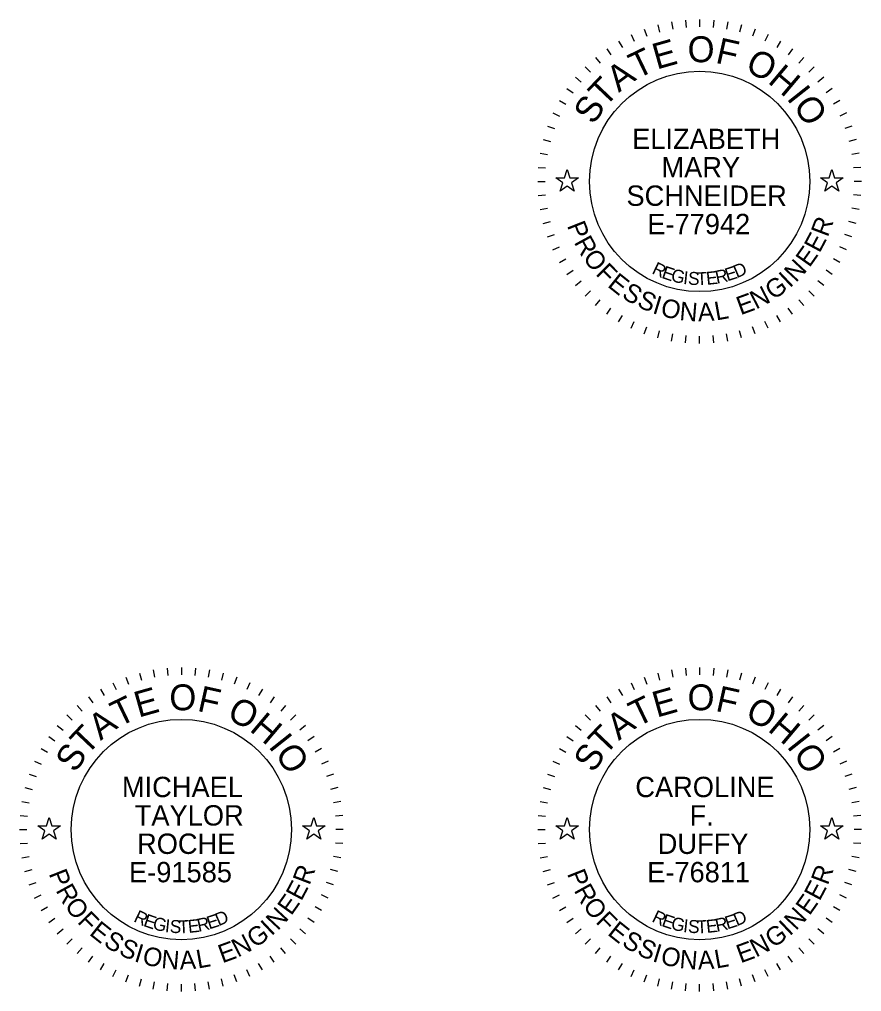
# Model space of a CAD drawing. Extents: x -21.9 to 47.3, y 14.1 to 48.7.
# Drawn here: x 24.13 to 28.67, y 20.77 to 26.02 of the extents above; entities that cross this region are included whole.
import ezdxf

# ---------------------------------------------------------------- set-up
doc = ezdxf.new("R2010")
doc.units = 0
doc.layers.add('SH_Seal', color=7, linetype='Continuous')

msp = doc.modelspace()

# ---------------------------------------------------------------- linework, layer by layer
at = {"layer": 'SH_Seal'}
for p, q in [((27.5735, 25.989), (27.5839, 25.9503)), ((27.6481, 26.0055), (27.655, 25.9661)), ((27.7237, 26.0155), (27.7272, 25.9756)), ((27.8, 26.0188), (27.8, 25.9788)), ((27.8763, 26.0155), (27.8728, 25.9756)), ((27.9519, 26.0055), (27.945, 25.9661)), ((28.0265, 25.989), (28.0161, 25.9503)), ((27.4302, 25.9368), (27.4471, 25.9006)), ((27.5007, 25.966), (27.5144, 25.9284)), ((28.0993, 25.966), (28.0856, 25.9284)), ((28.1698, 25.9368), (28.1529, 25.9006)), ((27.3625, 25.9016), (27.3825, 25.8669)), ((28.2375, 25.9016), (28.2175, 25.8669)), ((27.2981, 25.8605), (27.3211, 25.8278)), ((28.3019, 25.8605), (28.2789, 25.8278)), ((27.2376, 25.8141), (27.2633, 25.7834)), ((28.3624, 25.8141), (28.3367, 25.7834)), ((27.1813, 25.7625), (27.2096, 25.7342)), ((28.4187, 25.7625), (28.3904, 25.7342)), ((27.1297, 25.7062), (27.1604, 25.6805)), ((28.4703, 25.7062), (28.4396, 25.6805)), ((27.0832, 25.6457), (27.116, 25.6227)), ((28.5168, 25.6457), (28.484, 25.6227)), ((27.0422, 25.5813), (27.0769, 25.5613)), ((28.5578, 25.5813), (28.5231, 25.5613)), ((27.007, 25.5136), (27.0432, 25.4967)), ((28.593, 25.5136), (28.5568, 25.4967)), ((26.9778, 25.4431), (27.0154, 25.4294)), ((28.6222, 25.4431), (28.5846, 25.4294)), ((26.9548, 25.3703), (26.9935, 25.3599)), ((28.6452, 25.3703), (28.6065, 25.3599)), ((26.9383, 25.2957), (26.9777, 25.2888)), ((28.6617, 25.2957), (28.6223, 25.2888)), ((26.9283, 25.22), (26.9682, 25.2166)), ((28.6717, 25.22), (28.6318, 25.2166)), ((26.925, 25.1438), (26.965, 25.1438)), ((28.675, 25.1438), (28.635, 25.1438)), ((26.9283, 25.0675), (26.9682, 25.071)), ((28.6717, 25.0675), (28.6318, 25.071)), ((26.9383, 24.9918), (26.9777, 24.9988)), ((28.6617, 24.9918), (28.6223, 24.9988)), ((26.9548, 24.9173), (26.9935, 24.9277)), ((28.6452, 24.9173), (28.6065, 24.9277)), ((26.9778, 24.8445), (27.0154, 24.8582)), ((28.6222, 24.8445), (28.5846, 24.8582)), ((27.007, 24.774), (27.0432, 24.7909)), ((28.593, 24.774), (28.5568, 24.7909)), ((27.0422, 24.7063), (27.0769, 24.7263)), ((28.5578, 24.7063), (28.5231, 24.7263)), ((27.0832, 24.6419), (27.116, 24.6649)), ((28.5168, 24.6419), (28.484, 24.6649)), ((27.1297, 24.5813), (27.1604, 24.6071)), ((28.4703, 24.5813), (28.4396, 24.6071)), ((27.1813, 24.5251), (27.2096, 24.5534)), ((28.4187, 24.5251), (28.3904, 24.5534)), ((27.2376, 24.4735), (27.2633, 24.5041)), ((28.3624, 24.4735), (28.3367, 24.5041)), ((27.2981, 24.427), (27.3211, 24.4598)), ((27.3625, 24.386), (27.3825, 24.4207)), ((28.2375, 24.386), (28.2175, 24.4207)), ((28.3019, 24.427), (28.2789, 24.4598)), ((27.4302, 24.3508), (27.4471, 24.387)), ((28.1698, 24.3508), (28.1529, 24.387)), ((27.5007, 24.3216), (27.5144, 24.3591)), ((27.5735, 24.2986), (27.5839, 24.3372)), ((27.6481, 24.2821), (27.655, 24.3215)), ((27.7237, 24.2721), (27.7272, 24.312)), ((27.8, 24.2688), (27.8, 24.3088)), ((27.8763, 24.2721), (27.8728, 24.312)), ((27.9519, 24.2821), (27.945, 24.3215)), ((28.0265, 24.2986), (28.0161, 24.3372)), ((28.0993, 24.3216), (28.0856, 24.3591)), ((24.7735, 22.489), (24.7839, 22.4503)), ((24.8481, 22.5055), (24.855, 22.4661)), ((24.9237, 22.5155), (24.9272, 22.4756)), ((25, 22.5188), (25, 22.4788)), ((25.0763, 22.5155), (25.0728, 22.4756)), ((25.1519, 22.5055), (25.145, 22.4661)), ((25.2265, 22.489), (25.2161, 22.4503)), ((27.5735, 22.489), (27.5839, 22.4503)), ((27.6481, 22.5055), (27.655, 22.4661)), ((27.7237, 22.5155), (27.7272, 22.4756)), ((27.8, 22.5188), (27.8, 22.4788)), ((27.8763, 22.5155), (27.8728, 22.4756)), ((27.9519, 22.5055), (27.945, 22.4661)), ((28.0265, 22.489), (28.0161, 22.4503)), ((24.6302, 22.4368), (24.6471, 22.4006)), ((24.7007, 22.466), (24.7144, 22.4284)), ((25.2993, 22.466), (25.2856, 22.4284)), ((25.3698, 22.4368), (25.3529, 22.4006)), ((27.4302, 22.4368), (27.4471, 22.4006)), ((27.5007, 22.466), (27.5144, 22.4284)), ((28.0993, 22.466), (28.0856, 22.4284)), ((28.1698, 22.4368), (28.1529, 22.4006)), ((24.5625, 22.4016), (24.5825, 22.3669)), ((25.4375, 22.4016), (25.4175, 22.3669)), ((27.3625, 22.4016), (27.3825, 22.3669)), ((28.2375, 22.4016), (28.2175, 22.3669)), ((24.4376, 22.3141), (24.4633, 22.2834)), ((24.4981, 22.3605), (24.5211, 22.3278)), ((25.5019, 22.3605), (25.4789, 22.3278)), ((25.5624, 22.3141), (25.5367, 22.2834)), ((27.2376, 22.3141), (27.2633, 22.2834)), ((27.2981, 22.3605), (27.3211, 22.3278)), ((28.3019, 22.3605), (28.2789, 22.3278)), ((28.3624, 22.3141), (28.3367, 22.2834)), ((24.3813, 22.2625), (24.4096, 22.2342)), ((25.6187, 22.2625), (25.5904, 22.2342)), ((27.1813, 22.2625), (27.2096, 22.2342)), ((28.4187, 22.2625), (28.3904, 22.2342)), ((24.3297, 22.2062), (24.3604, 22.1805)), ((25.6703, 22.2062), (25.6396, 22.1805)), ((27.1297, 22.2062), (27.1604, 22.1805)), ((28.4703, 22.2062), (28.4396, 22.1805)), ((24.2832, 22.1457), (24.316, 22.1227)), ((25.7168, 22.1457), (25.684, 22.1227)), ((27.0832, 22.1457), (27.116, 22.1227)), ((28.5168, 22.1457), (28.484, 22.1227)), ((24.2422, 22.0813), (24.2769, 22.0613)), ((25.7578, 22.0813), (25.7231, 22.0613)), ((27.0422, 22.0813), (27.0769, 22.0613)), ((28.5578, 22.0813), (28.5231, 22.0613)), ((24.207, 22.0136), (24.2432, 21.9967)), ((25.793, 22.0136), (25.7568, 21.9967)), ((27.007, 22.0136), (27.0432, 21.9967)), ((28.593, 22.0136), (28.5568, 21.9967)), ((24.1778, 21.9431), (24.2154, 21.9294)), ((25.8222, 21.9431), (25.7846, 21.9294)), ((26.9778, 21.9431), (27.0154, 21.9294)), ((28.6222, 21.9431), (28.5846, 21.9294)), ((24.1548, 21.8703), (24.1935, 21.8599)), ((25.8452, 21.8703), (25.8065, 21.8599)), ((26.9548, 21.8703), (26.9935, 21.8599)), ((28.6452, 21.8703), (28.6065, 21.8599)), ((24.1383, 21.7957), (24.1777, 21.7888)), ((25.8617, 21.7957), (25.8223, 21.7888)), ((26.9383, 21.7957), (26.9777, 21.7888)), ((28.6617, 21.7957), (28.6223, 21.7888)), ((24.1283, 21.72), (24.1682, 21.7166)), ((25.8717, 21.72), (25.8318, 21.7166)), ((26.9283, 21.72), (26.9682, 21.7166)), ((28.6717, 21.72), (28.6318, 21.7166)), ((24.125, 21.6438), (24.165, 21.6438)), ((25.875, 21.6438), (25.835, 21.6438)), ((26.925, 21.6438), (26.965, 21.6438)), ((28.675, 21.6438), (28.635, 21.6438)), ((24.1283, 21.5675), (24.1682, 21.571)), ((25.8717, 21.5675), (25.8318, 21.571)), ((26.9283, 21.5675), (26.9682, 21.571)), ((28.6717, 21.5675), (28.6318, 21.571)), ((24.1383, 21.4918), (24.1777, 21.4988)), ((25.8617, 21.4918), (25.8223, 21.4988)), ((26.9383, 21.4918), (26.9777, 21.4988)), ((28.6617, 21.4918), (28.6223, 21.4988)), ((24.1548, 21.4173), (24.1935, 21.4277)), ((25.8452, 21.4173), (25.8065, 21.4277)), ((26.9548, 21.4173), (26.9935, 21.4277)), ((28.6452, 21.4173), (28.6065, 21.4277)), ((24.1778, 21.3445), (24.2154, 21.3582)), ((25.8222, 21.3445), (25.7846, 21.3582)), ((26.9778, 21.3445), (27.0154, 21.3582)), ((28.6222, 21.3445), (28.5846, 21.3582)), ((24.207, 21.274), (24.2432, 21.2909)), ((25.793, 21.274), (25.7568, 21.2909)), ((27.007, 21.274), (27.0432, 21.2909)), ((28.593, 21.274), (28.5568, 21.2909)), ((24.2422, 21.2063), (24.2769, 21.2263)), ((25.7578, 21.2063), (25.7231, 21.2263)), ((27.0422, 21.2063), (27.0769, 21.2263)), ((28.5578, 21.2063), (28.5231, 21.2263)), ((24.2832, 21.1419), (24.316, 21.1649)), ((25.7168, 21.1419), (25.684, 21.1649)), ((27.0832, 21.1419), (27.116, 21.1649)), ((28.5168, 21.1419), (28.484, 21.1649)), ((24.3297, 21.0813), (24.3604, 21.1071)), ((25.6703, 21.0813), (25.6396, 21.1071)), ((27.1297, 21.0813), (27.1604, 21.1071)), ((28.4703, 21.0813), (28.4396, 21.1071)), ((24.3813, 21.0251), (24.4096, 21.0534)), ((25.6187, 21.0251), (25.5904, 21.0534)), ((27.1813, 21.0251), (27.2096, 21.0534)), ((28.4187, 21.0251), (28.3904, 21.0534)), ((24.4376, 20.9735), (24.4633, 21.0041)), ((25.5624, 20.9735), (25.5367, 21.0041)), ((27.2376, 20.9735), (27.2633, 21.0041)), ((28.3624, 20.9735), (28.3367, 21.0041)), ((24.4981, 20.927), (24.5211, 20.9598)), ((25.5019, 20.927), (25.4789, 20.9598)), ((27.2981, 20.927), (27.3211, 20.9598)), ((28.3019, 20.927), (28.2789, 20.9598)), ((24.5625, 20.886), (24.5825, 20.9207)), ((25.4375, 20.886), (25.4175, 20.9207)), ((27.3625, 20.886), (27.3825, 20.9207)), ((28.2375, 20.886), (28.2175, 20.9207)), ((24.6302, 20.8508), (24.6471, 20.887)), ((24.7007, 20.8216), (24.7144, 20.8591)), ((25.2993, 20.8216), (25.2856, 20.8591)), ((25.3698, 20.8508), (25.3529, 20.887)), ((27.4302, 20.8508), (27.4471, 20.887)), ((27.5007, 20.8216), (27.5144, 20.8591)), ((28.0993, 20.8216), (28.0856, 20.8591)), ((28.1698, 20.8508), (28.1529, 20.887)), ((24.7735, 20.7986), (24.7839, 20.8372)), ((24.8481, 20.7821), (24.855, 20.8215)), ((24.9237, 20.7721), (24.9272, 20.812)), ((25, 20.7688), (25, 20.8088)), ((25.0763, 20.7721), (25.0728, 20.812)), ((25.1519, 20.7821), (25.145, 20.8215)), ((25.2265, 20.7986), (25.2161, 20.8372)), ((27.5735, 20.7986), (27.5839, 20.8372)), ((27.6481, 20.7821), (27.655, 20.8215)), ((27.7237, 20.7721), (27.7272, 20.812)), ((27.8, 20.7688), (27.8, 20.8088)), ((27.8763, 20.7721), (27.8728, 20.812)), ((27.9519, 20.7821), (27.945, 20.8215)), ((28.0265, 20.7986), (28.0161, 20.8372))]:
    msp.add_line(p, q, dxfattribs=at)
for points in [[(27.0236, 25.1638), (27.0705, 25.1638), (27.085, 25.2083), (27.0995, 25.1638), (27.1464, 25.1638), (27.1085, 25.1362), (27.123, 25.0916), (27.085, 25.1191), (27.047, 25.0916), (27.0615, 25.1362)], [(28.4536, 25.1638), (28.5005, 25.1638), (28.515, 25.2083), (28.5295, 25.1638), (28.5764, 25.1638), (28.5385, 25.1362), (28.553, 25.0916), (28.515, 25.1191), (28.477, 25.0916), (28.4915, 25.1362)], [(24.2236, 21.6638), (24.2705, 21.6638), (24.285, 21.7083), (24.2995, 21.6638), (24.3464, 21.6638), (24.3085, 21.6362), (24.323, 21.5916), (24.285, 21.6191), (24.247, 21.5916), (24.2615, 21.6362)], [(25.6536, 21.6638), (25.7005, 21.6638), (25.715, 21.7083), (25.7295, 21.6638), (25.7764, 21.6638), (25.7385, 21.6362), (25.753, 21.5916), (25.715, 21.6191), (25.677, 21.5916), (25.6915, 21.6362)], [(27.0236, 21.6638), (27.0705, 21.6638), (27.085, 21.7083), (27.0995, 21.6638), (27.1464, 21.6638), (27.1085, 21.6362), (27.123, 21.5916), (27.085, 21.6191), (27.047, 21.5916), (27.0615, 21.6362)], [(28.4536, 21.6638), (28.5005, 21.6638), (28.515, 21.7083), (28.5295, 21.6638), (28.5764, 21.6638), (28.5385, 21.6362), (28.553, 21.5916), (28.515, 21.6191), (28.477, 21.5916), (28.4915, 21.6362)]]:
    msp.add_lwpolyline(points, close=True, dxfattribs=at)
for centre in [(27.8, 25.1438), (25, 21.6438), (27.8, 21.6438)]:
    msp.add_circle(centre, 0.595, dxfattribs=at)

# ---------------------------------------------------------------- texts
for s, height, rotation, p in [('E', 0.14, 15.7571, (27.5684, 25.7476)), ('O', 0.14, 359.7812, (27.7347, 25.788)), ('F', 0.14, 347.4362, (27.8811, 25.7855)), ('T', 0.14, 25.7167, (27.4616, 25.6956)), ('O', 0.14, 332.2586, (28.0398, 25.7453)), ('A', 0.14, 36.4747, (27.3634, 25.6219)), ('H', 0.14, 319.9136, (28.1632, 25.6799)), ('T', 0.14, 46.4344, (27.2883, 25.5402)), ('I', 0.14, 308.367, (28.2665, 25.5921)), ('S', 0.14, 57.1924, (27.2281, 25.4452)), ('O', 0.14, 303.1491, (28.3021, 25.5527)), ('R', 0.1, 69.2322, (28.4919, 24.8392)), ('P', 0.1, 291.494, (27.0823, 24.9058)), ('R', 0.1, 298.7311, (27.119, 24.8155)), ('E', 0.1, 61.9951, (28.4476, 24.7536)), ('E', 0.1, 54.758, (28.3933, 24.6752)), ('O', 0.1, 306.4666, (27.1655, 24.7321)), ('F', 0.1, 314.7068, (27.2343, 24.6421)), ('R', 0.07, 334.487, (27.5375, 24.6488)), ('E', 0.07, 341.04, (27.5906, 24.6238)), ('E', 0.07, 17.6836, (27.9498, 24.604)), ('D', 0.07, 23.3052, (28.001, 24.6208)), ('N', 0.1, 47.0224, (28.3202, 24.5946)), ('E', 0.1, 321.4393, (27.2978, 24.5786)), ('G', 0.07, 347.4752, (27.6414, 24.6056)), ('I', 0.07, 353.7858, (27.7091, 24.5906)), ('S', 0.07, 356.8926, (27.7358, 24.5867)), ('T', 0.07, 3.0061, (27.7857, 24.5825)), ('E', 0.07, 6.0117, (27.8389, 24.585)), ('R', 0.07, 11.9184, (27.8925, 24.5912)), ('G', 0.1, 35.0469, (28.1981, 24.5008)), ('I', 0.1, 43.287, (28.2868, 24.5652)), ('S', 0.1, 328.6764, (27.3743, 24.519)), ('N', 0.1, 27.3113, (28.1045, 24.4513)), ('S', 0.1, 335.9134, (27.4564, 24.4704)), ('I', 0.1, 343.1505, (27.5406, 24.4335)), ('E', 0.1, 20.0742, (28.0212, 24.4208)), ('O', 0.1, 346.8859, (27.5839, 24.4189)), ('N', 0.1, 355.1261, (27.6888, 24.3955)), ('A', 0.1, 2.8617, (27.7923, 24.3875)), ('L', 0.1, 10.0987, (27.8894, 24.3928)), ('O', 0.14, 359.7812, (24.9347, 22.288)), ('F', 0.14, 347.4362, (25.0811, 22.2855)), ('O', 0.14, 359.7812, (27.7347, 22.288)), ('F', 0.14, 347.4362, (27.8811, 22.2855)), ('T', 0.14, 25.7167, (24.6616, 22.1956)), ('E', 0.14, 15.7571, (24.7684, 22.2476)), ('T', 0.14, 25.7167, (27.4616, 22.1956)), ('E', 0.14, 15.7571, (27.5684, 22.2476)), ('O', 0.14, 332.2586, (25.2398, 22.2453)), ('O', 0.14, 332.2586, (28.0398, 22.2453)), ('A', 0.14, 36.4747, (24.5634, 22.1219)), ('H', 0.14, 319.9136, (25.3632, 22.1799)), ('A', 0.14, 36.4747, (27.3634, 22.1219)), ('H', 0.14, 319.9136, (28.1632, 22.1799)), ('T', 0.14, 46.4344, (24.4883, 22.0402)), ('T', 0.14, 46.4344, (27.2883, 22.0402)), ('I', 0.14, 308.367, (25.4665, 22.0921)), ('I', 0.14, 308.367, (28.2665, 22.0921)), ('S', 0.14, 57.1924, (24.4281, 21.9452)), ('S', 0.14, 57.1924, (27.2281, 21.9452)), ('O', 0.14, 303.1491, (25.5021, 22.0527)), ('O', 0.14, 303.1491, (28.3021, 22.0527)), ('P', 0.1, 291.494, (24.2823, 21.4058)), ('R', 0.1, 69.2322, (25.6919, 21.3392)), ('P', 0.1, 291.494, (27.0823, 21.4058)), ('R', 0.1, 69.2322, (28.4919, 21.3392)), ('E', 0.1, 61.9951, (25.6476, 21.2536)), ('E', 0.1, 61.9951, (28.4476, 21.2536)), ('R', 0.1, 298.7311, (24.319, 21.3155)), ('R', 0.1, 298.7311, (27.119, 21.3155)), ('O', 0.1, 306.4666, (24.3655, 21.2321)), ('E', 0.1, 54.758, (25.5933, 21.1752)), ('O', 0.1, 306.4666, (27.1655, 21.2321)), ('E', 0.1, 54.758, (28.3933, 21.1752)), ('N', 0.1, 47.0224, (25.5202, 21.0946)), ('N', 0.1, 47.0224, (28.3202, 21.0946)), ('F', 0.1, 314.7068, (24.4343, 21.1421)), ('R', 0.07, 334.487, (24.7375, 21.1488)), ('E', 0.07, 341.04, (24.7906, 21.1238)), ('G', 0.07, 347.4752, (24.8414, 21.1056)), ('I', 0.07, 353.7858, (24.9091, 21.0906)), ('E', 0.07, 6.0117, (25.0389, 21.085)), ('R', 0.07, 11.9184, (25.0925, 21.0912)), ('E', 0.07, 17.6836, (25.1498, 21.104)), ('D', 0.07, 23.3052, (25.201, 21.1208)), ('F', 0.1, 314.7068, (27.2343, 21.1421)), ('R', 0.07, 334.487, (27.5375, 21.1488)), ('E', 0.07, 341.04, (27.5906, 21.1238)), ('G', 0.07, 347.4752, (27.6414, 21.1056)), ('I', 0.07, 353.7858, (27.7091, 21.0906)), ('E', 0.07, 6.0117, (27.8389, 21.085)), ('R', 0.07, 11.9184, (27.8925, 21.0912)), ('E', 0.07, 17.6836, (27.9498, 21.104)), ('D', 0.07, 23.3052, (28.001, 21.1208)), ('E', 0.1, 321.4393, (24.4978, 21.0786)), ('S', 0.07, 356.8926, (24.9358, 21.0867)), ('T', 0.07, 3.0061, (24.9857, 21.0825)), ('G', 0.1, 35.0469, (25.3981, 21.0008)), ('I', 0.1, 43.287, (25.4868, 21.0652)), ('E', 0.1, 321.4393, (27.2978, 21.0786)), ('S', 0.07, 356.8926, (27.7358, 21.0867)), ('T', 0.07, 3.0061, (27.7857, 21.0825)), ('G', 0.1, 35.0469, (28.1981, 21.0008)), ('I', 0.1, 43.287, (28.2868, 21.0652)), ('S', 0.1, 328.6764, (24.5743, 21.019)), ('N', 0.1, 27.3113, (25.3045, 20.9513)), ('S', 0.1, 328.6764, (27.3743, 21.019)), ('N', 0.1, 27.3113, (28.1045, 20.9513)), ('S', 0.1, 335.9134, (24.6564, 20.9704)), ('I', 0.1, 343.1505, (24.7406, 20.9335)), ('O', 0.1, 346.8859, (24.7839, 20.9189)), ('E', 0.1, 20.0742, (25.2212, 20.9208)), ('S', 0.1, 335.9134, (27.4564, 20.9704)), ('I', 0.1, 343.1505, (27.5406, 20.9335)), ('O', 0.1, 346.8859, (27.5839, 20.9189)), ('E', 0.1, 20.0742, (28.0212, 20.9208)), ('N', 0.1, 355.1261, (24.8888, 20.8955)), ('A', 0.1, 2.8617, (24.9923, 20.8875)), ('L', 0.1, 10.0987, (25.0894, 20.8928)), ('N', 0.1, 355.1261, (27.6888, 20.8955)), ('A', 0.1, 2.8617, (27.7923, 20.8875)), ('L', 0.1, 10.0987, (27.8894, 20.8928))]:
    msp.add_text(s, height=height, rotation=rotation, dxfattribs=at).set_placement(p)
for s, p in [('ELIZABETH', (27.4353, 25.3187)), ('MARY', (27.5938, 25.1654)), ('SCHNEIDER', (27.4047, 25.0121)), ('E-77942', (27.5172, 24.8589)), ('MICHAEL', (24.6789, 21.8187)), ('CAROLINE', (27.4526, 21.8187)), ('TAYLOR', (24.7481, 21.6654)), ('F.', (27.7459, 21.6654)), ('ROCHE', (24.7606, 21.5121)), ('DUFFY', (27.5735, 21.5121)), ('E-91585', (24.7173, 21.3589)), ('E-76811', (27.5167, 21.3589))]:
    msp.add_text(s, height=0.11, dxfattribs=at).set_placement(p)

doc.saveas('drawing.dxf')
